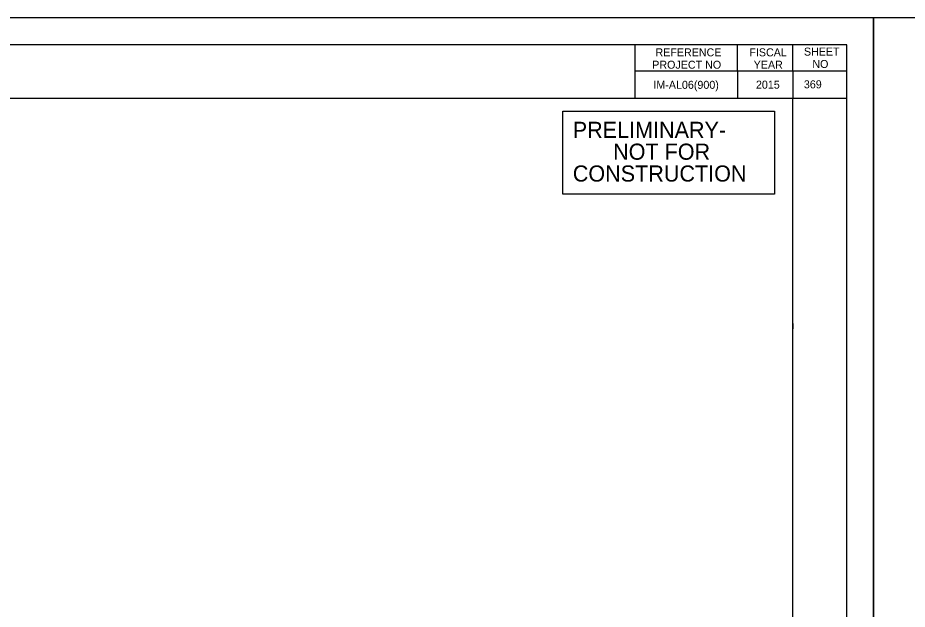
# Model space of a CAD drawing. Extents: x 1797478 to 1805176, y 246529 to 250952.
# Drawn here: x 1802296.8 to 1802462.3, y 250174.4 to 250284.4 of the extents above; entities that cross this region are included whole.
import ezdxf

# ---------------------------------------------------------------- set-up
doc = ezdxf.new("R2010")
doc.units = 0
for name, color, linetype in [('1', 7, 'Continuous'), ('2', 7, 'Continuous'), ('ANNO-SHT', 7, 'Continuous'), ('Level 6', 7, 'Continuous'), ('Level 62', 7, 'Continuous'), ('SHT-BDR', 7, 'Continuous'), ('SHT-BNDRY', 7, 'Continuous')]:
    doc.layers.add(name, color=color, linetype=linetype)

msp = doc.modelspace()

# ---------------------------------------------------------------- linework, layer by layer
at = {"layer": '1'}
msp.add_lwpolyline([(1802398.17, 250267.06), (1802437.57, 250267.06), (1802437.57, 250251.62), (1802398.17, 250251.62)], close=True, dxfattribs=at)
at = {"layer": '2'}
msp.add_lwpolyline([(1802440.97, 250227.57), (1802440.98, 250226.57)], dxfattribs=at)
msp.add_lwpolyline([(1802440.97, 250227.57), (1802440.98, 250226.57)], dxfattribs=at)
at = {"layer": 'Level 6'}
for p, q in [((1802411.55, 250279.42), (1802411.55, 250269.43)), ((1802430.71, 250274.42), (1802430.71, 250279.42)), ((1802441, 250274.55), (1802441, 250279.42)), ((1802451, 250274.48), (1802411.55, 250274.48)), ((1802430.71, 250274.42), (1802430.71, 250269.43)), ((1802441, 250274.55), (1802441, 250269.43)), ((1802451, 250269.43), (1802412.76, 250269.43))]:
    msp.add_line(p, q, dxfattribs=at)
at = {"layer": 'Level 62'}
for points in [[(1802116, 250064.42), (1802456, 250064.42), (1802456, 250284.42), (1802116, 250284.42)], [(1802456, 250064.42), (1802796, 250064.42), (1802796, 250284.42), (1802456, 250284.42)]]:
    msp.add_lwpolyline(points, close=True, dxfattribs=at)
at = {"layer": 'SHT-BDR'}
msp.add_lwpolyline([(1802141, 250079.43), (1802441, 250079.43), (1802441, 250269.43), (1802141, 250269.43)], close=True, dxfattribs=at)
at = {"layer": 'SHT-BNDRY'}
msp.add_lwpolyline([(1802128.5, 250069.42), (1802451, 250069.42), (1802451, 250279.42), (1802128.5, 250279.42)], close=True, dxfattribs=at)

# ---------------------------------------------------------------- texts
at = {"layer": '1'}
for s, p in [('PRELIMINARY-', (1802400.03, 250262.08)), ('NOT FOR', (1802407.54, 250258.02)), ('CONSTRUCTION', (1802400.04, 250253.96))]:
    msp.add_text(s, height=3, dxfattribs=at).set_placement(p)
at = {"layer": 'ANNO-SHT'}
for s, height, p in [('IM-AL06(900)', 1.4899, (1802415.03, 250271.21)), ('2015', 1.49, (1802434.11, 250271.24)), ('  369  ', 1.49, (1802441.92, 250271.3))]:
    msp.add_text(s, height=height, rotation=360, dxfattribs=at).set_placement(p)
at = {"layer": 'Level 6'}
for s, p in [('SHEET', (1802443.04, 250277.39)), ('REFERENCE', (1802415.42, 250277.25)), ('FISCAL', (1802432.89, 250277.25)), ('PROJECT NO', (1802414.82, 250274.95)), ('YEAR', (1802433.69, 250274.95)), ('NO', (1802444.61, 250275.09))]:
    msp.add_text(s, height=1.488, dxfattribs=at).set_placement(p)

doc.saveas('drawing.dxf')
